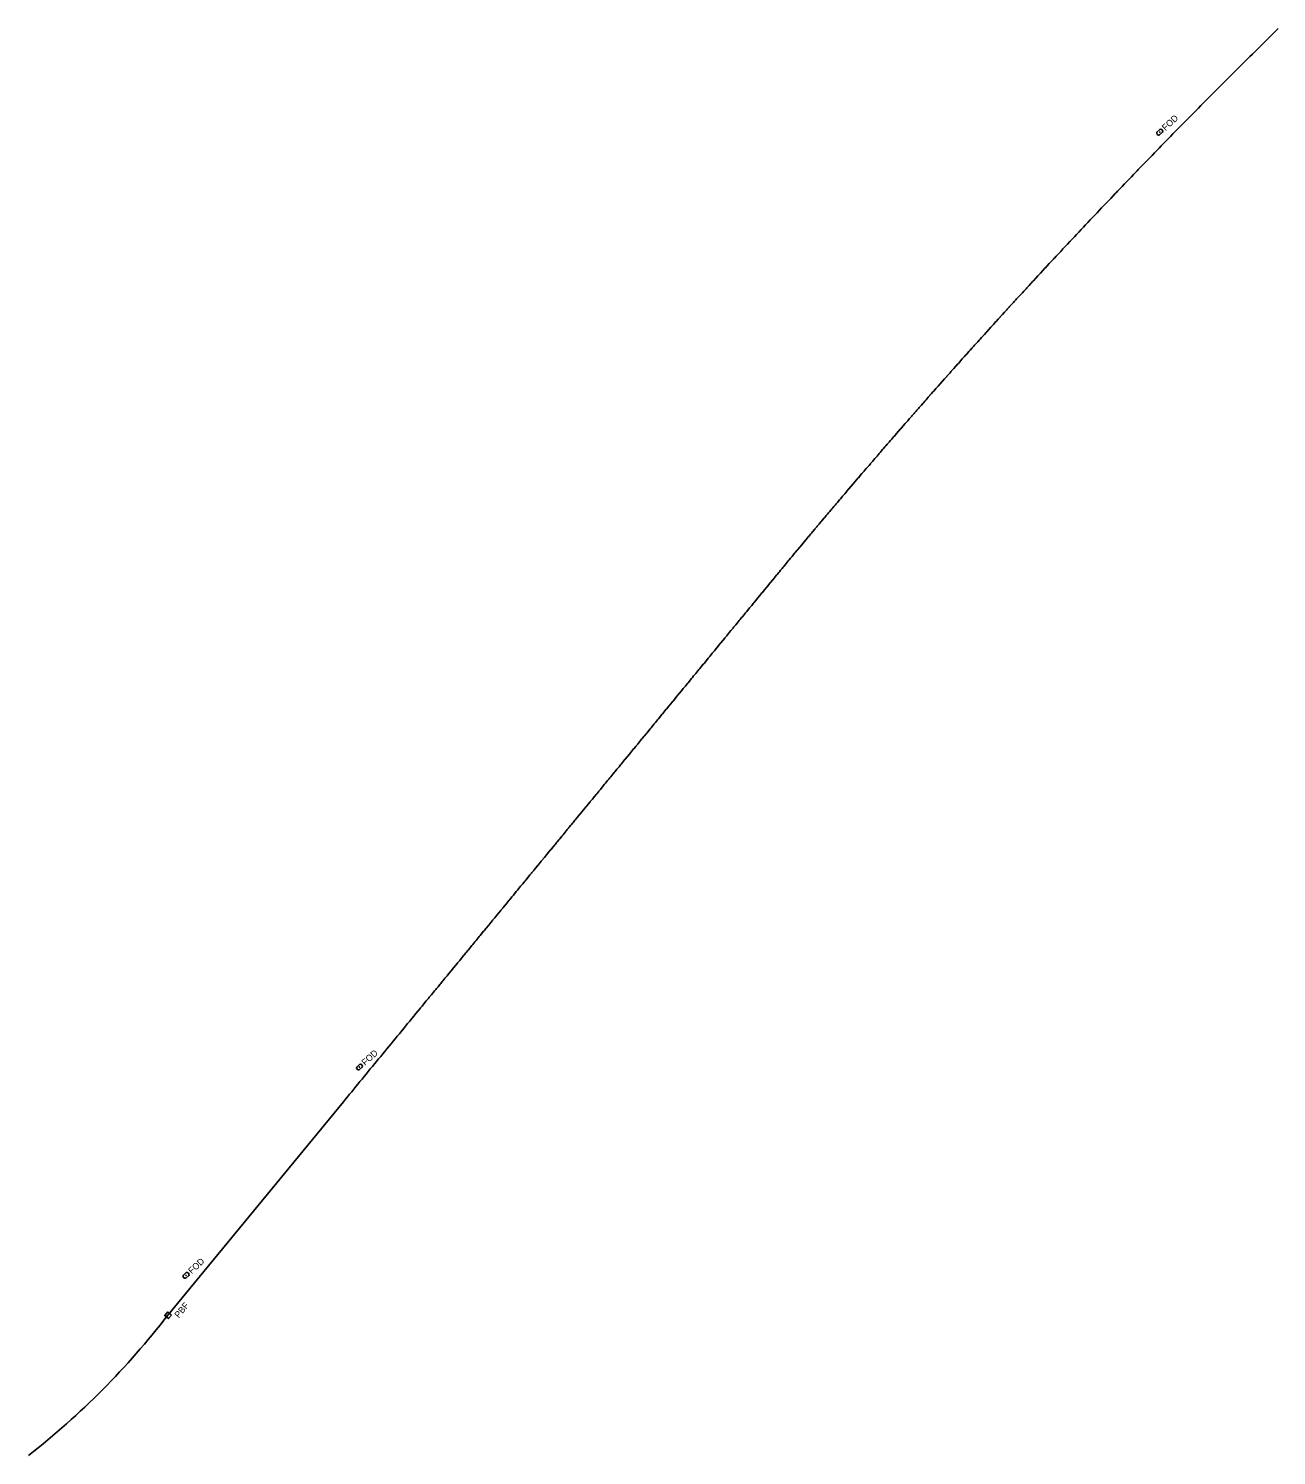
# Model space of a CAD drawing. Extents: x 1738869 to 1765295, y 463516 to 481552.
# Drawn here: x 1759261.8 to 1759644.3, y 480500.6 to 480938 of the extents above; entities that cross this region are included whole.
import ezdxf

# ---------------------------------------------------------------- set-up
doc = ezdxf.new("R2010")
doc.units = 0
for name, color, linetype in [('D_ITS_Fiber', 7, 'Continuous'), ('D_ITS_JuctionBox', 7, 'Continuous'), ('ITS Sign FO Delineator', 7, 'Continuous')]:
    doc.layers.add(name, color=color, linetype=linetype)

msp = doc.modelspace()

# ---------------------------------------------------------------- linework, layer by layer
at = {"layer": 'D_ITS_Fiber'}
for points in [[(1759576.23, 480867.62), (1759576.78, 480868.2), (1759576.96, 480868.39), (1759577.47, 480868.95), (1759578.16, 480869.69), (1759578.86, 480870.43), (1759579.55, 480871.17), (1759580.25, 480871.91), (1759580.94, 480872.66), (1759581.64, 480873.4), (1759582.35, 480874.16), (1759582.38, 480874.19), (1759583.03, 480874.88), (1759583.72, 480875.62), (1759584.42, 480876.36), (1759585.11, 480877.09), (1759585.81, 480877.83), (1759586.51, 480878.58), (1759587.21, 480879.31), (1759587.9, 480880.05), (1759588.6, 480880.78), (1759588.71, 480880.9), (1759589.31, 480881.53), (1759590, 480882.26), (1759590.7, 480883), (1759591.4, 480883.73), (1759592.1, 480884.47), (1759592.8, 480885.21), (1759593.5, 480885.94), (1759594.2, 480886.67), (1759594.9, 480887.4), (1759595.14, 480887.65), (1759595.61, 480888.15), (1759596.31, 480888.88), (1759597.01, 480889.61), (1759597.71, 480890.34), (1759598.42, 480891.08), (1759599.12, 480891.81), (1759599.83, 480892.54), (1759600.53, 480893.28), (1759601.24, 480894.01), (1759601.61, 480894.39), (1759601.94, 480894.73), (1759602.64, 480895.47), (1759603.35, 480896.2), (1759604.05, 480896.93), (1759604.76, 480897.66), (1759605.47, 480898.39), (1759606.17, 480899.12), (1759606.89, 480899.85), (1759607.59, 480900.57), (1759608.1, 480901.1), (1759608.31, 480901.31), (1759609.01, 480902.03), (1759609.72, 480902.76), (1759610.42, 480903.48), (1759611.13, 480904.21), (1759611.85, 480904.94), (1759612.56, 480905.67), (1759613.27, 480906.39), (1759613.97, 480907.11), (1759614.63, 480907.78), (1759614.69, 480907.85), (1759615.4, 480908.57), (1759616.11, 480909.29), (1759616.82, 480910.01), (1759617.54, 480910.74), (1759618.25, 480911.46), (1759618.96, 480912.18), (1759619.67, 480912.91), (1759620.39, 480913.63), (1759621.1, 480914.35), (1759621.17, 480914.42), (1759621.82, 480915.07), (1759622.54, 480915.8), (1759623.25, 480916.52), (1759623.96, 480917.24), (1759624.68, 480917.96), (1759625.4, 480918.68), (1759626.11, 480919.4), (1759626.83, 480920.12), (1759627.54, 480920.83), (1759627.75, 480921.04), (1759628.27, 480921.55), (1759628.99, 480922.28), (1759629.7, 480922.99), (1759630.42, 480923.71), (1759631.14, 480924.43), (1759631.86, 480925.14), (1759632.58, 480925.86), (1759633.3, 480926.57), (1759634.02, 480927.29), (1759634.37, 480927.64), (1759634.74, 480928.01), (1759635.46, 480928.72), (1759636.18, 480929.44), (1759636.91, 480930.15), (1759637.63, 480930.87), (1759638.35, 480931.58), (1759639.08, 480932.3), (1759639.8, 480933.01), (1759640.52, 480933.72), (1759641.01, 480934.2), (1759641.25, 480934.43), (1759641.97, 480935.15), (1759642.7, 480935.86), (1759643.42, 480936.57), (1759644.14, 480937.28), (1759644.87, 480937.99)], [(1759304.45, 480543.57), (1759304.55, 480543.69), (1759358.3, 480609.02), (1759358.93, 480609.79), (1759359.57, 480610.57), (1759360.2, 480611.34), (1759360.83, 480612.11), (1759361.47, 480612.89), (1759362.11, 480613.66), (1759362.74, 480614.43), (1759363.38, 480615.2), (1759364.01, 480615.98), (1759364.65, 480616.75), (1759365.28, 480617.52), (1759365.92, 480618.29), (1759366.55, 480619.07), (1759367.19, 480619.84), (1759367.82, 480620.61), (1759368.46, 480621.38), (1759369.1, 480622.16), (1759369.73, 480622.93), (1759370.36, 480623.7), (1759371, 480624.47), (1759371.64, 480625.25), (1759372.27, 480626.01), (1759372.91, 480626.79), (1759373.55, 480627.56), (1759374.18, 480628.33), (1759374.81, 480629.1), (1759375.45, 480629.88), (1759376.09, 480630.65), (1759376.72, 480631.42), (1759377.35, 480632.19), (1759377.99, 480632.97), (1759378.62, 480633.74), (1759379.26, 480634.51), (1759379.9, 480635.28), (1759380.53, 480636.06), (1759381.16, 480636.82), (1759381.8, 480637.6), (1759381.97, 480637.8), (1759382.44, 480638.37), (1759382.63, 480638.6), (1759383.07, 480639.14), (1759383.29, 480639.41), (1759383.71, 480639.92), (1759383.96, 480640.22), (1759384.34, 480640.69), (1759384.63, 480641.04), (1759384.98, 480641.46), (1759385.29, 480641.85), (1759385.62, 480642.24), (1759385.96, 480642.66), (1759386.25, 480643), (1759386.62, 480643.46), (1759386.88, 480643.77), (1759387.3, 480644.28), (1759387.52, 480644.55), (1759387.96, 480645.08), (1759388.15, 480645.32), (1759388.62, 480645.89), (1759388.79, 480646.1), (1759389.3, 480646.71), (1759389.43, 480646.87), (1759389.97, 480647.52), (1759390.07, 480647.65), (1759390.64, 480648.35), (1759390.71, 480648.43), (1759391.26, 480649.1), (1759391.3, 480649.14), (1759392.06, 480650.07), (1759392.06, 480650.07), (1759392.62, 480650.75), (1759392.64, 480650.78), (1759393.26, 480651.53), (1759393.32, 480651.6), (1759393.87, 480652.26), (1759393.95, 480652.37), (1759394.51, 480653.05), (1759394.63, 480653.19), (1759394.95, 480653.58), (1759395.14, 480653.82), (1759395.29, 480654), (1759395.77, 480654.58), (1759395.96, 480654.81), (1759396.41, 480655.36), (1759396.62, 480655.62), (1759397.05, 480656.13), (1759397.29, 480656.42), (1759397.69, 480656.91), (1759397.96, 480657.25), (1759398.32, 480657.68), (1759398.62, 480658.05), (1759398.95, 480658.45), (1759399.29, 480658.86), (1759399.59, 480659.23), (1759399.95, 480659.66), (1759400.22, 480659.99), (1759400.63, 480660.48), (1759400.86, 480660.77), (1759401.29, 480661.29), (1759401.5, 480661.55), (1759401.95, 480662.1), (1759402.13, 480662.31), (1759402.62, 480662.91), (1759402.77, 480663.09), (1759403.28, 480663.71), (1759403.39, 480663.85), (1759403.96, 480664.54), (1759404.04, 480664.64), (1759404.62, 480665.34), (1759404.67, 480665.4), (1759405.31, 480666.18), (1759405.33, 480666.2), (1759405.87, 480666.86), (1759405.88, 480666.87), (1759406.55, 480667.68), (1759406.59, 480667.73), (1759407.23, 480668.51), (1759407.3, 480668.6), (1759407.84, 480669.25), (1759407.95, 480669.38), (1759408.49, 480670.04), (1759408.62, 480670.2), (1759409.12, 480670.81), (1759409.29, 480671.02), (1759409.75, 480671.58), (1759409.95, 480671.82), (1759410.39, 480672.36), (1759410.62, 480672.63), (1759411.02, 480673.12), (1759411.28, 480673.44), (1759411.65, 480673.89), (1759411.95, 480674.26), (1759412.3, 480674.67), (1759412.62, 480675.06), (1759412.93, 480675.44), (1759413.28, 480675.87), (1759413.57, 480676.22), (1759413.95, 480676.69), (1759414.2, 480676.98), (1759414.62, 480677.49), (1759414.84, 480677.76), (1759415.28, 480678.3), (1759415.48, 480678.54), (1759415.94, 480679.1), (1759416.1, 480679.29), (1759416.62, 480679.93), (1759416.75, 480680.08), (1759417.28, 480680.72), (1759417.37, 480680.84), (1759417.92, 480681.51), (1759417.99, 480681.59), (1759418.63, 480682.37), (1759418.66, 480682.41), (1759418.96, 480682.77), (1759418.96, 480682.78), (1759419.89, 480683.9), (1759419.91, 480683.93), (1759420.55, 480684.71), (1759420.61, 480684.78), (1759421.19, 480685.48), (1759421.28, 480685.59), (1759421.82, 480686.24), (1759421.94, 480686.39), (1759422.46, 480687.03), (1759422.61, 480687.21), (1759423.1, 480687.8), (1759423.29, 480688.03), (1759423.73, 480688.57), (1759423.94, 480688.83), (1759424.37, 480689.35), (1759424.61, 480689.64), (1759425, 480690.11), (1759425.28, 480690.46), (1759425.63, 480690.88), (1759425.94, 480691.26), (1759426.27, 480691.66), (1759426.61, 480692.07), (1759426.9, 480692.43), (1759427.28, 480692.88), (1759427.34, 480692.96), (1759427.54, 480693.2), (1759427.95, 480693.7), (1759428.18, 480693.98), (1759428.61, 480694.5), (1759428.81, 480694.75), (1759429.27, 480695.31), (1759429.45, 480695.52), (1759429.95, 480696.13), (1759430.08, 480696.29), (1759430.61, 480696.94), (1759430.72, 480697.07), (1759431.29, 480697.76), (1759431.37, 480697.85), (1759431.91, 480698.52), (1759431.96, 480698.58), (1759432.65, 480699.41), (1759432.66, 480699.43), (1759433.3, 480700.2), (1759433.31, 480700.21), (1759433.92, 480700.96), (1759433.97, 480701.02), (1759434.52, 480701.69), (1759434.6, 480701.79), (1759435.16, 480702.46), (1759435.27, 480702.6), (1759435.79, 480703.24), (1759435.93, 480703.4), (1759436.44, 480704.02), (1759436.62, 480704.23), (1759437.07, 480704.78), (1759437.27, 480705.03), (1759437.7, 480705.56), (1759437.93, 480705.84), (1759438.35, 480706.34), (1759438.61, 480706.66), (1759438.98, 480707.1), (1759439.27, 480707.46), (1759439.61, 480707.87), (1759439.94, 480708.27), (1759440.25, 480708.65), (1759440.6, 480709.08), (1759440.88, 480709.42), (1759441.28, 480709.9), (1759441.52, 480710.2), (1759441.94, 480710.7), (1759442.15, 480710.96), (1759442.6, 480711.51), (1759442.78, 480711.73), (1759443.27, 480712.32), (1759443.43, 480712.51), (1759443.94, 480713.14), (1759444.06, 480713.28), (1759444.61, 480713.95), (1759444.7, 480714.06), (1759445.27, 480714.75), (1759445.33, 480714.83), (1759445.95, 480715.58), (1759445.98, 480715.61), (1759446.28, 480715.98), (1759446.28, 480715.99), (1759447.25, 480717.16), (1759447.28, 480717.2), (1759447.89, 480717.94), (1759447.96, 480718.02), (1759448.5, 480718.68), (1759448.6, 480718.8), (1759449.15, 480719.47), (1759449.27, 480719.62), (1759449.78, 480720.24), (1759449.94, 480720.44), (1759450.41, 480721), (1759450.6, 480721.23), (1759451.05, 480721.78), (1759451.27, 480722.04), (1759451.68, 480722.55), (1759451.93, 480722.85), (1759452.32, 480723.33), (1759452.61, 480723.67), (1759452.95, 480724.09), (1759453.27, 480724.48), (1759453.59, 480724.87), (1759453.93, 480725.28), (1759454.23, 480725.64), (1759454.6, 480726.1), (1759454.86, 480726.41), (1759455.27, 480726.91), (1759455.49, 480727.18), (1759455.93, 480727.72), (1759456.13, 480727.96), (1759456.59, 480728.52), (1759456.76, 480728.72), (1759457.27, 480729.34), (1759457.4, 480729.51), (1759457.93, 480730.14), (1759458.03, 480730.26), (1759458.58, 480730.93), (1759458.65, 480731.02), (1759459.3, 480731.81), (1759459.34, 480731.86), (1759459.75, 480732.36), (1759459.97, 480732.63), (1759459.97, 480732.63), (1759460.01, 480732.67), (1759460.53, 480733.31), (1759460.55, 480733.33), (1759461.24, 480734.17), (1759461.29, 480734.23), (1759461.84, 480734.9), (1759461.92, 480735), (1759462.48, 480735.67), (1759462.59, 480735.81), (1759463.12, 480736.46), (1759463.26, 480736.63), (1759463.76, 480737.23), (1759463.94, 480737.45), (1759464.39, 480737.99), (1759464.59, 480738.24), (1759465.03, 480738.77), (1759465.26, 480739.05), (1759465.66, 480739.54), (1759465.93, 480739.87), (1759466.29, 480740.31), (1759466.59, 480740.68), (1759466.93, 480741.08), (1759467.26, 480741.49), (1759467.56, 480741.86), (1759467.92, 480742.29), (1759468.2, 480742.63), (1759468.6, 480743.11), (1759468.83, 480743.4), (1759469.26, 480743.92), (1759469.47, 480744.17), (1759469.92, 480744.72), (1759470.11, 480744.95), (1759470.6, 480745.54), (1759470.74, 480745.72), (1759471.26, 480746.35), (1759471.38, 480746.5), (1759471.92, 480747.15), (1759472, 480747.25), (1759472.57, 480747.94), (1759472.62, 480748.01), (1759473.28, 480748.8), (1759473.3, 480748.83), (1759474.01, 480749.7), (1759474.02, 480749.7), (1759474.56, 480750.36), (1759474.6, 480750.41), (1759475.17, 480751.1), (1759475.23, 480751.18), (1759475.82, 480751.89), (1759475.92, 480752.01), (1759476.45, 480752.66), (1759476.58, 480752.82), (1759477.1, 480753.45), (1759477.27, 480753.65), (1759477.73, 480754.21), (1759477.92, 480754.45), (1759478.36, 480754.98), (1759478.58, 480755.25), (1759479, 480755.76), (1759479.26, 480756.08), (1759479.63, 480756.53), (1759479.92, 480756.88), (1759480.27, 480757.31), (1759480.59, 480757.69), (1759480.9, 480758.07), (1759481.25, 480758.49), (1759481.54, 480758.84), (1759481.92, 480759.31), (1759482.18, 480759.62), (1759482.59, 480760.12), (1759482.81, 480760.39), (1759483.26, 480760.93), (1759483.45, 480761.17), (1759483.92, 480761.74), (1759484.08, 480761.94), (1759484.59, 480762.56), (1759484.72, 480762.71), (1759485.26, 480763.37), (1759485.36, 480763.49), (1759485.89, 480764.14), (1759485.96, 480764.23), (1759486.59, 480764.99), (1759486.63, 480765.03), (1759487.35, 480765.91), (1759487.35, 480765.92), (1759487.91, 480766.59), (1759487.94, 480766.62), (1759488.55, 480767.37), (1759488.61, 480767.44), (1759489.16, 480768.11), (1759489.24, 480768.21), (1759489.81, 480768.9), (1759489.85, 480768.95), (1759489.9, 480769.01), (1759490.44, 480769.66), (1759490.59, 480769.85), (1759491.1, 480770.46), (1759491.28, 480770.69), (1759491.72, 480771.22), (1759491.94, 480771.49), (1759492.31, 480771.93), (1759492.6, 480772.32), (1759492.77, 480772.49), (1759493.02, 480772.8), (1759493.3, 480773.14), (1759493.68, 480773.59), (1759493.99, 480773.97), (1759494.33, 480774.37), (1759494.66, 480774.78), (1759494.97, 480775.15), (1759495.34, 480775.6), (1759495.62, 480775.94), (1759495.81, 480776.16), (1759496.03, 480776.42), (1759496.27, 480776.72), (1759496.71, 480777.25), (1759496.92, 480777.5), (1759497.38, 480778.05), (1759497.56, 480778.27), (1759498.07, 480778.88), (1759498.21, 480779.05), (1759498.77, 480779.72), (1759498.88, 480779.85), (1759499.44, 480780.53), (1759499.53, 480780.63), (1759500.12, 480781.34), (1759500.18, 480781.4), (1759500.79, 480782.14), (1759500.82, 480782.17), (1759501.49, 480782.98), (1759501.5, 480782.99), (1759501.78, 480783.33), (1759502.13, 480783.74), (1759502.18, 480783.8), (1759502.77, 480784.5), (1759502.84, 480784.59), (1759503.43, 480785.29), (1759503.55, 480785.43), (1759504.08, 480786.06), (1759504.22, 480786.23), (1759504.74, 480786.85), (1759504.91, 480787.05), (1759505.39, 480787.62), (1759505.59, 480787.86), (1759505.84, 480788.16), (1759506.05, 480788.4), (1759506.28, 480788.68), (1759506.7, 480789.18), (1759506.97, 480789.5), (1759507.36, 480789.95), (1759507.65, 480790.3), (1759507.79, 480790.47), (1759508.01, 480790.73), (1759508.34, 480791.12), (1759508.67, 480791.5), (1759509.03, 480791.94), (1759509.32, 480792.28), (1759509.73, 480792.76), (1759509.98, 480793.06), (1759510.4, 480793.55), (1759510.64, 480793.83), (1759511.1, 480794.38), (1759511.3, 480794.61), (1759511.78, 480795.18), (1759511.95, 480795.38), (1759512.47, 480795.99), (1759512.6, 480796.14), (1759513.16, 480796.79), (1759513.26, 480796.91), (1759513.86, 480797.62), (1759513.87, 480797.64), (1759513.92, 480797.69), (1759514.54, 480798.42), (1759516.13, 480800.29), (1759516.15, 480800.3), (1759516.58, 480800.8), (1759516.64, 480800.88), (1759517.22, 480801.55), (1759517.32, 480801.67), (1759517.88, 480802.32), (1759518, 480802.47), (1759518.55, 480803.1), (1759518.71, 480803.29), (1759519.21, 480803.88), (1759519.41, 480804.1), (1759519.85, 480804.61), (1759519.88, 480804.65), (1759520.09, 480804.9), (1759520.53, 480805.41), (1759520.79, 480805.71), (1759521.19, 480806.18), (1759521.48, 480806.52), (1759521.86, 480806.95), (1759522.18, 480807.33), (1759522.53, 480807.72), (1759522.88, 480808.13), (1759523.18, 480808.48), (1759523.57, 480808.94), (1759523.85, 480809.26), (1759524.28, 480809.75), (1759524.52, 480810.03), (1759524.97, 480810.55), (1759525.18, 480810.8), (1759525.67, 480811.35), (1759525.84, 480811.56), (1759526, 480811.74), (1759526.36, 480812.16), (1759526.52, 480812.33), (1759527.06, 480812.95), (1759527.17, 480813.08), (1759527.77, 480813.77), (1759527.85, 480813.86), (1759528.44, 480814.54), (1759528.49, 480814.6), (1759529.11, 480815.31), (1759529.12, 480815.33), (1759529.88, 480816.19), (1759529.9, 480816.21), (1759530.52, 480816.93), (1759530.57, 480816.98), (1759531.17, 480817.68), (1759531.26, 480817.78), (1759531.85, 480818.46), (1759531.97, 480818.59), (1759532.14, 480818.79), (1759532.52, 480819.22), (1759532.66, 480819.38), (1759533.2, 480819.99), (1759533.38, 480820.2), (1759533.85, 480820.74), (1759534.07, 480820.99), (1759534.53, 480821.51), (1759534.77, 480821.78), (1759535.2, 480822.27), (1759535.48, 480822.59), (1759535.87, 480823.04), (1759536.18, 480823.39), (1759536.54, 480823.8), (1759536.89, 480824.19), (1759537.21, 480824.56), (1759537.59, 480824.99), (1759537.89, 480825.32), (1759538.09, 480825.55), (1759538.1, 480825.56), (1759538.56, 480826.09), (1759539, 480826.58), (1759539.23, 480826.84), (1759539.71, 480827.39), (1759539.91, 480827.61), (1759540.41, 480828.18), (1759540.58, 480828.37), (1759541.13, 480828.99), (1759541.25, 480829.13), (1759541.83, 480829.77), (1759541.93, 480829.89), (1759542.56, 480830.6), (1759542.62, 480830.67), (1759543.23, 480831.35), (1759543.26, 480831.39), (1759544.14, 480832.38), (1759544.15, 480832.38), (1759544.5, 480832.78), (1759544.6, 480832.89), (1759544.63, 480832.93), (1759545.31, 480833.68), (1759545.38, 480833.76), (1759545.96, 480834.42), (1759546.07, 480834.54), (1759546.65, 480835.19), (1759546.79, 480835.34), (1759547.33, 480835.95), (1759547.5, 480836.14), (1759548.01, 480836.71), (1759548.21, 480836.94), (1759548.68, 480837.46), (1759548.91, 480837.72), (1759549.37, 480838.22), (1759549.64, 480838.53), (1759550.04, 480838.98), (1759550.34, 480839.31), (1759550.42, 480839.4), (1759550.43, 480839.41), (1759551.06, 480840.11), (1759551.4, 480840.49), (1759551.77, 480840.9), (1759552.08, 480841.24), (1759552.48, 480841.69), (1759552.76, 480842), (1759553.19, 480842.48), (1759553.44, 480842.76), (1759553.91, 480843.27), (1759554.12, 480843.5), (1759554.61, 480844.05), (1759554.79, 480844.25), (1759555.34, 480844.86), (1759555.49, 480845.02), (1759556.05, 480845.64), (1759556.16, 480845.76), (1759556.77, 480846.43), (1759556.84, 480846.51), (1759556.98, 480846.66), (1759557.47, 480847.21), (1759557.52, 480847.26), (1759558.23, 480848.04), (1759558.24, 480848.05), (1759558.98, 480848.86), (1759559, 480848.89), (1759559.56, 480849.5), (1759559.62, 480849.57), (1759560.26, 480850.27), (1759560.35, 480850.37), (1759560.94, 480851.02), (1759561.07, 480851.16), (1759561.62, 480851.77), (1759561.77, 480851.93), (1759562.32, 480852.54), (1759562.51, 480852.74), (1759563, 480853.27), (1759563.26, 480853.56), (1759563.3, 480853.6), (1759563.68, 480854.02), (1759563.94, 480854.3), (1759564.37, 480854.78), (1759564.66, 480855.09), (1759565.06, 480855.52), (1759565.38, 480855.88), (1759565.75, 480856.27), (1759566.11, 480856.67), (1759566.43, 480857.02), (1759566.82, 480857.44), (1759567.12, 480857.77), (1759567.54, 480858.23), (1759567.81, 480858.52), (1759568.27, 480859.02), (1759568.49, 480859.26), (1759568.98, 480859.79), (1759569.18, 480860.01), (1759569.57, 480860.43), (1759569.7, 480860.57), (1759569.88, 480860.76), (1759570.44, 480861.37), (1759570.57, 480861.51), (1759571.15, 480862.14), (1759571.24, 480862.24), (1759571.9, 480862.95), (1759571.96, 480863.01), (1759572.67, 480863.78), (1759572.7, 480863.81), (1759573.45, 480864.62), (1759573.46, 480864.63), (1759574.02, 480865.23), (1759574.06, 480865.28), (1759574.68, 480865.94), (1759574.75, 480866.02), (1759575.41, 480866.74), (1759575.52, 480866.85), (1759575.92, 480867.28), (1759576.09, 480867.46), (1759576.23, 480867.62)]]:
    msp.add_lwpolyline(points, dxfattribs=at)
msp.add_arc((1759112.18, 480691.84), 242.8, 308.0354, 322.3599, dxfattribs=at)
at = {"layer": 'D_ITS_JuctionBox'}
msp.add_lwpolyline([(1759305.62, 480543.66), (1759304.66, 480542.54), (1759303.54, 480543.49), (1759304.49, 480544.61)], close=True, dxfattribs=at)
at = {"layer": 'ITS Sign FO Delineator'}
for p, q in [((1759607.68, 480906.21), (1759608.6, 480907.05)), ((1759609.36, 480906.22), (1759608.44, 480905.38)), ((1759362.37, 480619.65), (1759363.29, 480620.5)), ((1759364.06, 480619.67), (1759363.13, 480618.82)), ((1759309.22, 480555.8), (1759310.14, 480556.65)), ((1759310.9, 480555.82), (1759309.98, 480554.97))]:
    msp.add_line(p, q, dxfattribs=at)
for centre in [(1759608.52, 480906.22), (1759363.21, 480619.66), (1759310.06, 480555.81)]:
    msp.add_circle(centre, 0.05, dxfattribs=at)
for centre, major_axis in [((1759608.06, 480905.79), (0.38, -0.414)), ((1759608.98, 480906.64), (-0.38, 0.414)), ((1759362.75, 480619.24), (0.38, -0.414)), ((1759363.67, 480620.08), (-0.38, 0.414)), ((1759309.6, 480555.39), (0.38, -0.414)), ((1759310.52, 480556.23), (-0.38, 0.414))]:
    msp.add_ellipse(centre, major_axis=major_axis, ratio=0.666667, start_param=3.141593, end_param=6.283185, dxfattribs=at)

# ---------------------------------------------------------------- texts
at = {"layer": 'D_ITS_JuctionBox'}
msp.add_text('PBF', height=1.964, rotation=49.8013, dxfattribs=at).set_placement((1759307.82, 480542.61))
at = {"layer": 'ITS Sign FO Delineator'}
for p in [(1759610.28, 480906.53), (1759364.97, 480619.97), (1759311.81, 480556.12)]:
    msp.add_text('FOD', height=1.968, rotation=42.5495, dxfattribs=at).set_placement(p)

doc.saveas('drawing.dxf')
